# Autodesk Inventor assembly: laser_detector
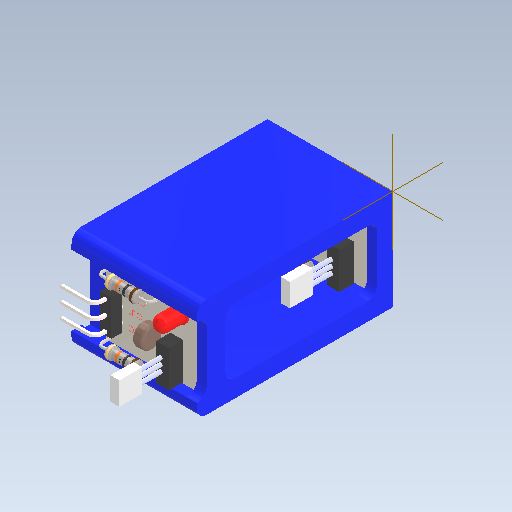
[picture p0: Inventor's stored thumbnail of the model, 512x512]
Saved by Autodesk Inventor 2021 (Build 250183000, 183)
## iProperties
Created: 2026-10
Part Number: laser_detector
Document SubType Name: Assembly
Designer: alolo
Author: alolo
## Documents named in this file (3)
- C:\Users\alolo\Documents\Inventor\Design 1\laser_detector.iam
- C:\Users\alolo\Documents\Inventor\Design 1\laser_detector_rack.ipt
- C:\Users\alolo\Documents\Inventor\Design 1\Laser Detection Hardware.ipt
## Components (3 placed, 2 different names)
1. laser_detector_rack:1 — Mate:1, Mate:2, Mate:3, Mate:4, Mate:5, Mate:6, Mate:7, Mate:8, Mate:9
2. Laser Detection Hardware:1 — Mate:4, Mate:5, Mate:6
3. Laser Detection Hardware:2 — Mate:7, Mate:8, Mate:9
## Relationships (9: Mate 9)
- Mate:1: laser_detector_rack:1
- Mate:2: laser_detector_rack:1
- Mate:3: laser_detector_rack:1
- Mate:4: laser_detector_rack:1 ↔ Laser Detection Hardware:1
- Mate:5: laser_detector_rack:1 ↔ Laser Detection Hardware:1
- Mate:6: laser_detector_rack:1 ↔ Laser Detection Hardware:1
- Mate:7: laser_detector_rack:1 ↔ Laser Detection Hardware:2
- Mate:8: laser_detector_rack:1 ↔ Laser Detection Hardware:2
- Mate:9: laser_detector_rack:1 ↔ Laser Detection Hardware:2
